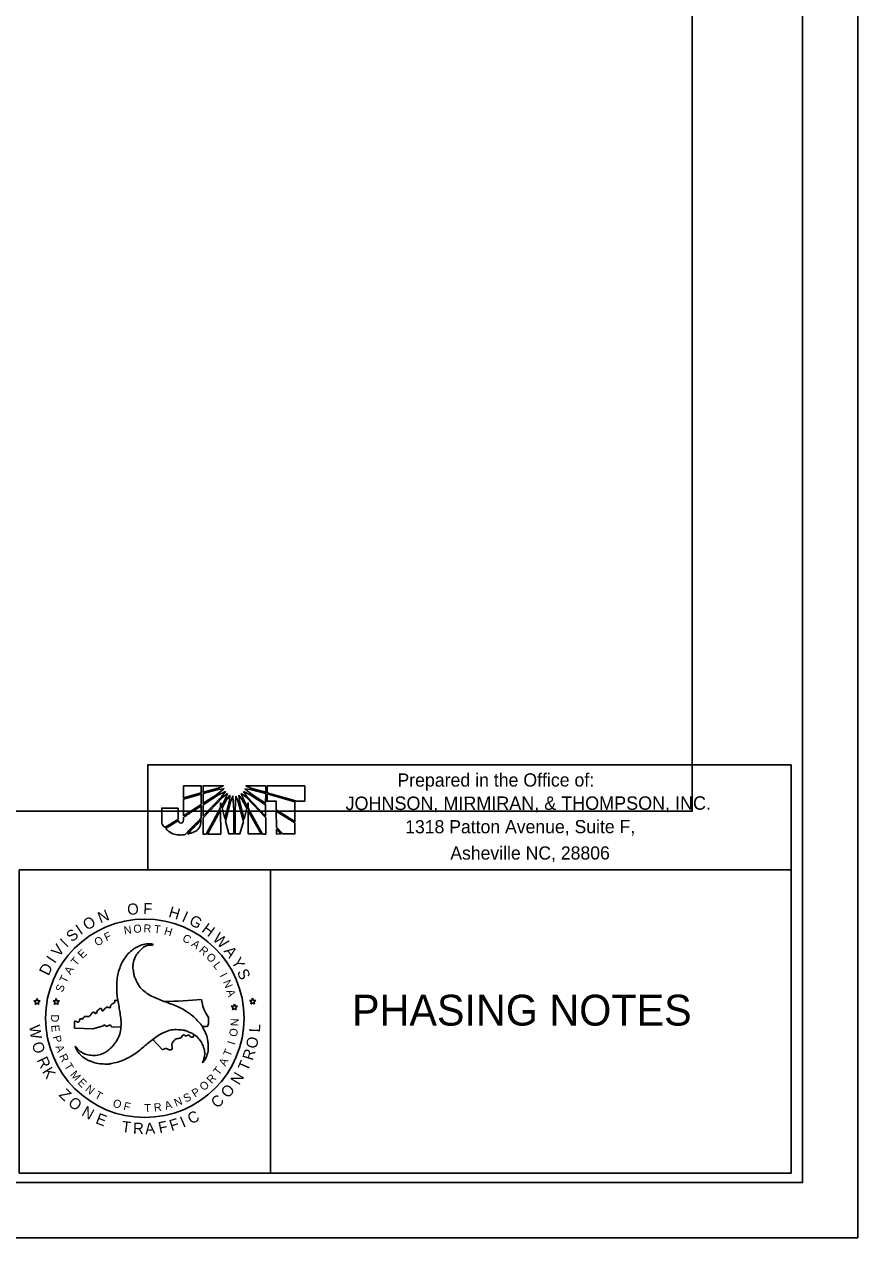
# Model space of a CAD drawing. Extents: x 764226 to 769781, y 650021 to 652521.
# Drawn here: x 767760 to 768137, y 650021 to 650571 of the extents above; entities that cross this region are included whole.
import ezdxf

# ---------------------------------------------------------------- set-up
doc = ezdxf.new("R2010")
doc.units = 0
for name, color, linetype in [('Default', 7, 'Continuous'), ('DEV BORDER CELL', 7, 'Continuous'), ('DEV DOT SWIRL SEAL CELL', 7, 'Continuous'), ('Scratch_Level_0', 7, 'Continuous'), ('Sheet Plan CELL', 7, 'Continuous'), ('Sheet Plot Border Outside CELL', 7, 'Continuous'), ('Sheet Title CELL', 7, 'Continuous'), ('Text', 7, 'Continuous')]:
    doc.layers.add(name, color=color, linetype=linetype)

msp = doc.modelspace()

# ---------------------------------------------------------------- linework, layer by layer
at = {"layer": 'Default'}
for p, q in [((767839.76, 650225.87), (767831.66, 650225.87)), ((767831.66, 650225.87), (767831.67, 650220.5)), ((767831.67, 650220.5), (767839.76, 650222.75)), ((767839.76, 650222.16), (767831.67, 650219.88)), ((767839.76, 650222.75), (767839.76, 650225.87)), ((767839.77, 650217.47), (767839.76, 650222.16)), ((767849.71, 650225.92), (767840.6, 650225.91)), ((767840.6, 650225.91), (767840.6, 650223.02)), ((767840.6, 650223.02), (767847.39, 650224.89)), ((767847.39, 650224.26), (767840.61, 650222.39)), ((767840.61, 650222.39), (767840.61, 650218.01)), ((767840.61, 650218.01), (767846.68, 650221.86)), ((767847.62, 650221.77), (767840.61, 650217.3)), ((767840.61, 650212.25), (767849.14, 650221.14)), ((767846.68, 650221.86), (767850.04, 650224.59)), ((767847.39, 650224.89), (767849.71, 650225.92)), ((767850.04, 650224.59), (767847.39, 650224.26)), ((767850.7, 650223.33), (767847.62, 650221.77)), ((767849.14, 650221.14), (767850.7, 650223.33)), ((767851.64, 650222.36), (767849.49, 650220.7)), ((767850.65, 650219.76), (767851.64, 650222.36)), ((767852.8, 650221.64), (767851.2, 650219.58)), ((767852.58, 650219.14), (767852.8, 650221.64)), ((767854.14, 650221.28), (767853.03, 650218.68)), ((767854.49, 650214.89), (767854.14, 650221.28)), ((767855.48, 650221.28), (767855.07, 650214.89)), ((767856.55, 650218.69), (767855.48, 650221.28)), ((767856.77, 650221.64), (767857.04, 650219.05)), ((767858.34, 650219.58), (767856.77, 650221.64)), ((767857.92, 650222.36), (767858.91, 650219.77)), ((767860.07, 650220.71), (767857.92, 650222.36)), ((767858.87, 650223.34), (767860.43, 650221.11)), ((767862, 650221.78), (767858.87, 650223.34)), ((767859.58, 650224.6), (767862.97, 650221.82)), ((767862.07, 650224.28), (767859.58, 650224.6)), ((767869.01, 650225.9), (767860.03, 650225.93)), ((767860.03, 650225.93), (767862.3, 650224.87)), ((767860.43, 650221.11), (767868.96, 650212.18)), ((767868.96, 650217.36), (767862, 650221.78)), ((767869.01, 650222.37), (767862.07, 650224.28)), ((767862.3, 650224.87), (767869.01, 650222.99)), ((767862.97, 650221.82), (767868.96, 650218.08)), ((767868.96, 650218.08), (767869.01, 650222.37)), ((767869.01, 650222.99), (767869.01, 650225.9)), ((767886.65, 650225.96), (767869.63, 650225.94)), ((767869.63, 650225.94), (767869.64, 650222.81)), ((767869.64, 650222.81), (767869.64, 650222.72)), ((767869.64, 650222.72), (767883.04, 650218.98)), ((767869.64, 650222.24), (767869.64, 650222.19)), ((767882.19, 650218.67), (767869.64, 650222.24)), ((767869.64, 650222.19), (767869.64, 650218.93)), ((767886.66, 650218.98), (767886.65, 650225.96)), ((767831.67, 650219.88), (767831.68, 650212.33)), ((767831.68, 650212.33), (767839.77, 650217.47)), ((767840.61, 650217.3), (767840.61, 650212.25)), ((767849.49, 650220.7), (767840.62, 650211.39)), ((767841.96, 650204.05), (767848.56, 650216.01)), ((767848.56, 650216.01), (767848.56, 650218.15)), ((767848.56, 650218.15), (767848.96, 650216.68)), ((767848.96, 650216.68), (767850.65, 650219.76)), ((767851.2, 650219.58), (767849.19, 650215.92)), ((767849.19, 650215.92), (767850.49, 650211.05)), ((767850.49, 650211.05), (767852.58, 650219.14)), ((767853.03, 650218.68), (767850.76, 650209.93)), ((767858.88, 650209.81), (767856.55, 650218.69)), ((767857.04, 650219.05), (767859.15, 650210.87)), ((767860.44, 650215.79), (767858.34, 650219.58)), ((767858.91, 650219.77), (767860.65, 650216.55)), ((767859.15, 650210.87), (767860.44, 650215.79)), ((767868.97, 650211.34), (767860.07, 650220.71)), ((767860.65, 650216.55), (767861.06, 650218.16)), ((767861.06, 650218.16), (767861.07, 650215.79)), ((767861.07, 650215.79), (767867.54, 650204.07)), ((767868.96, 650212.18), (767868.96, 650217.36)), ((767869.64, 650218.93), (767873.8, 650218.93)), ((767873.8, 650218.93), (767873.8, 650215.04)), ((767882.19, 650209.73), (767882.19, 650218.67)), ((767883.04, 650218.98), (767886.66, 650218.98)), ((767840.62, 650211.39), (767840.62, 650204.04)), ((767848.56, 650214.85), (767842.59, 650204.05)), ((767848.62, 650204.05), (767848.56, 650214.85)), ((767854.5, 650204.1), (767854.49, 650214.89)), ((767855.07, 650214.89), (767855.08, 650204.1)), ((767866.87, 650204.11), (767861.07, 650214.63)), ((767861.07, 650214.63), (767861.08, 650204.1)), ((767868.97, 650204.07), (767868.97, 650211.34)), ((767873.8, 650215.04), (767882.19, 650209.73)), ((767873.8, 650214.37), (767873.81, 650207.13)), ((767882.19, 650209.1), (767873.8, 650214.37)), ((767850.76, 650209.93), (767852.29, 650204.09)), ((767857.32, 650204.1), (767858.88, 650209.81)), ((767873.81, 650207.13), (767876.71, 650204.08)), ((767875.91, 650204.08), (767873.81, 650206.35)), ((767873.81, 650206.35), (767873.81, 650204.07)), ((767882.2, 650204.08), (767882.19, 650209.1)), ((767840.62, 650204.04), (767841.96, 650204.05)), ((767842.59, 650204.05), (767848.62, 650204.05)), ((767852.29, 650204.09), (767854.5, 650204.1)), ((767855.08, 650204.1), (767857.32, 650204.1)), ((767861.08, 650204.1), (767866.87, 650204.11)), ((767867.54, 650204.07), (767868.97, 650204.07)), ((767873.81, 650204.07), (767875.91, 650204.08)), ((767876.71, 650204.08), (767882.2, 650204.08))]:
    msp.add_line(p, q, dxfattribs=at)
for points in [[(767831.67, 650220.5), (767839.76, 650222.75), (767839.76, 650225.87), (767831.66, 650225.87), (767831.67, 650220.5)], [(767831.68, 650212.33), (767839.77, 650217.47), (767839.76, 650222.16), (767831.67, 650219.88), (767831.68, 650212.33)], [(767847.39, 650224.89), (767849.71, 650225.92), (767840.6, 650225.91), (767840.6, 650223.02), (767847.39, 650224.89)], [(767840.61, 650222.39), (767840.61, 650218.01), (767846.68, 650221.86), (767850.04, 650224.59), (767847.39, 650224.26), (767840.61, 650222.39)], [(767840.61, 650217.3), (767840.61, 650212.25), (767849.14, 650221.14), (767850.7, 650223.33), (767847.62, 650221.77), (767840.61, 650217.3)], [(767851.64, 650222.36), (767849.49, 650220.7), (767840.62, 650211.39), (767840.62, 650204.04), (767841.96, 650204.05), (767848.56, 650216.01), (767848.56, 650218.15), (767848.96, 650216.68), (767850.65, 650219.76), (767851.64, 650222.36)], [(767852.8, 650221.64), (767851.2, 650219.58), (767849.19, 650215.92), (767850.49, 650211.05), (767852.58, 650219.14), (767852.8, 650221.64)], [(767853.03, 650218.68), (767850.76, 650209.93), (767852.29, 650204.09), (767854.5, 650204.1), (767854.49, 650214.89), (767854.14, 650221.28), (767853.03, 650218.68)], [(767855.48, 650221.28), (767855.07, 650214.89), (767855.08, 650204.1), (767857.32, 650204.1), (767858.88, 650209.81), (767856.55, 650218.69), (767855.48, 650221.28)], [(767856.77, 650221.64), (767857.04, 650219.05), (767859.15, 650210.87), (767860.44, 650215.79), (767858.34, 650219.58), (767856.77, 650221.64)], [(767857.92, 650222.36), (767858.91, 650219.77), (767860.65, 650216.55), (767861.06, 650218.16), (767861.07, 650215.79), (767867.54, 650204.07), (767868.97, 650204.07), (767868.97, 650211.34), (767860.07, 650220.71), (767857.92, 650222.36)], [(767858.87, 650223.34), (767860.43, 650221.11), (767868.96, 650212.18), (767868.96, 650217.36), (767862, 650221.78), (767858.87, 650223.34)], [(767859.58, 650224.6), (767862.97, 650221.82), (767868.96, 650218.08), (767869.01, 650222.37), (767862.07, 650224.28), (767859.58, 650224.6)], [(767862.3, 650224.87), (767869.01, 650222.99), (767869.01, 650225.9), (767860.03, 650225.93), (767862.3, 650224.87)], [(767869.64, 650222.24), (767869.64, 650222.19), (767869.64, 650218.93), (767873.8, 650218.93), (767873.8, 650215.04), (767882.19, 650209.73), (767882.19, 650218.67), (767869.64, 650222.24)], [(767842.59, 650204.05), (767848.62, 650204.05), (767848.56, 650214.85), (767842.59, 650204.05)], [(767861.08, 650204.1), (767866.87, 650204.11), (767861.07, 650214.63), (767861.08, 650204.1)], [(767873.8, 650214.37), (767873.81, 650207.13), (767876.71, 650204.08), (767882.2, 650204.08), (767882.19, 650209.1), (767873.8, 650214.37), (767873.8, 650214.37)], [(767873.81, 650204.07), (767873.81, 650204.07), (767875.91, 650204.08), (767873.81, 650206.35), (767873.81, 650204.07)]]:
    msp.add_lwpolyline(points, dxfattribs=at)
for points in [[(767829.35, 650215.8), (767829.35, 650215.8), (767821.85, 650215.8), (767821.85, 650215.8), (767821.85, 650215.8), (767821.86, 650211.11), (767821.86, 650211.11), (767821.86, 650211.11), (767821.86, 650210.61), (767821.86, 650210.61), (767821.86, 650209.14), (767822.34, 650207.98), (767823.2, 650207.01), (767823.2, 650207.01), (767829.35, 650210.75), (767829.35, 650210.85), (767829.35, 650210.85), (767829.35, 650215.8), (767829.35, 650215.8)], [(767829.35, 650215.8), (767829.35, 650215.8), (767821.85, 650215.8), (767821.85, 650215.8), (767821.85, 650215.8), (767821.86, 650211.11), (767821.86, 650211.11), (767821.86, 650211.11), (767821.86, 650210.61), (767821.86, 650210.61), (767821.86, 650209.14), (767822.34, 650207.98), (767823.2, 650207.01), (767823.2, 650207.01), (767829.35, 650210.75), (767829.35, 650210.85), (767829.35, 650210.85), (767829.35, 650215.8), (767829.35, 650215.8)], [(767830.52, 650209.06), (767830.04, 650209.06), (767829.62, 650209.32), (767829.45, 650210.22), (767829.45, 650210.22), (767823.64, 650206.62), (767823.64, 650206.62), (767825.43, 650204.74), (767828.29, 650203.62), (767830.71, 650203.62), (767831.34, 650203.62), (767831.82, 650203.68), (767832.49, 650203.81), (767832.49, 650203.81), (767839.77, 650211.35), (767839.77, 650211.35), (767839.77, 650211.35), (767839.77, 650216.8), (767839.77, 650216.8), (767839.77, 650216.8), (767831.68, 650211.65), (767831.68, 650211.65), (767831.68, 650209.61), (767831.18, 650209.06), (767830.52, 650209.06)], [(767830.52, 650209.06), (767830.04, 650209.06), (767829.62, 650209.32), (767829.45, 650210.22), (767829.45, 650210.22), (767823.64, 650206.62), (767823.64, 650206.62), (767825.43, 650204.74), (767828.29, 650203.62), (767830.71, 650203.62), (767831.34, 650203.62), (767831.82, 650203.68), (767832.49, 650203.81), (767832.49, 650203.81), (767839.77, 650211.35), (767839.77, 650211.35), (767839.77, 650211.35), (767839.77, 650216.8), (767839.77, 650216.8), (767839.77, 650216.8), (767831.68, 650211.65), (767831.68, 650211.65), (767831.68, 650209.61), (767831.18, 650209.06), (767830.52, 650209.06)], [(767839.77, 650210.5), (767839.77, 650210.5), (767833.47, 650203.98), (767833.47, 650203.98), (767836.56, 650204.75), (767839.63, 650206.8), (767839.77, 650210.5)], [(767839.77, 650210.5), (767839.77, 650210.5), (767833.47, 650203.98), (767833.47, 650203.98), (767836.56, 650204.75), (767839.63, 650206.8), (767839.77, 650210.5)]]:
    msp.add_open_spline(points, degree=3, dxfattribs=at)
at = {"layer": 'DEV BORDER CELL'}
for points in [[(768112.34, 651096.08), (766612.34, 651096.09), (766612.34, 650046.08), (768112.34, 650046.08)], [(767757.19, 650187.85), (767871.19, 650187.85), (767871.19, 650050.35), (767757.19, 650050.35)], [(768107.19, 650187.85), (767871.19, 650187.85), (767871.19, 650050.35), (768107.19, 650050.35)]]:
    msp.add_lwpolyline(points, close=True, dxfattribs=at)
at = {"layer": 'DEV DOT SWIRL SEAL CELL'}
for p, q in [((767763.92, 650128.51), (767764.8, 650127.87)), ((767765, 650128.51), (767763.92, 650128.51)), ((767764.8, 650127.87), (767764.48, 650126.83)), ((767765.32, 650129.52), (767765, 650128.51)), ((767765.68, 650128.51), (767765.32, 650129.52)), ((767766.77, 650128.51), (767765.68, 650128.51)), ((767765.89, 650127.87), (767766.77, 650128.51)), ((767765.89, 650127.87), (767766.77, 650128.51)), ((767766.21, 650126.83), (767765.89, 650127.87)), ((767766.21, 650126.83), (767765.89, 650127.87)), ((767773.68, 650128.5), (767772.6, 650128.5)), ((767772.6, 650128.5), (767773.48, 650127.86)), ((767773.48, 650127.86), (767773.16, 650126.81)), ((767774, 650129.5), (767773.68, 650128.5)), ((767774.36, 650128.5), (767774, 650129.5)), ((767775.45, 650128.5), (767774.36, 650128.5)), ((767774.56, 650127.86), (767775.45, 650128.5)), ((767774.89, 650126.81), (767774.56, 650127.86)), ((767862.73, 650128.66), (767861.64, 650128.66)), ((767861.64, 650128.66), (767862.53, 650128.01)), ((767862.53, 650128.01), (767862.2, 650126.97)), ((767862.2, 650126.97), (767863.05, 650127.61)), ((767863.05, 650129.66), (767862.73, 650128.66)), ((767863.41, 650128.66), (767863.05, 650129.66)), ((767863.05, 650127.61), (767863.93, 650126.97)), ((767864.49, 650128.66), (767863.41, 650128.66)), ((767863.61, 650128.01), (767864.49, 650128.66)), ((767863.93, 650126.97), (767863.61, 650128.01)), ((767764.48, 650126.83), (767765.32, 650127.47)), ((767765.32, 650127.47), (767766.21, 650126.83)), ((767765.32, 650127.47), (767766.21, 650126.83)), ((767773.16, 650126.81), (767774, 650127.46)), ((767774, 650127.46), (767774.89, 650126.81)), ((767854.45, 650126.01), (767853.37, 650126.01)), ((767853.37, 650126.01), (767854.25, 650125.37)), ((767854.25, 650125.37), (767853.93, 650124.33)), ((767853.93, 650124.33), (767854.77, 650124.97)), ((767854.77, 650127.01), (767854.45, 650126.01)), ((767855.13, 650126.01), (767854.77, 650127.01)), ((767854.77, 650124.97), (767855.65, 650124.33)), ((767856.22, 650126.01), (767855.13, 650126.01)), ((767855.33, 650125.37), (767856.22, 650126.01)), ((767855.65, 650124.33), (767855.33, 650125.37)), ((767782.25, 650116.07), (767782.33, 650118.73)), ((767795.44, 650117.17), (767790.64, 650115.76)), ((767799.14, 650116.61), (767803.36, 650116.57)), ((767790.64, 650115.76), (767782.25, 650116.07)), ((767817.89, 650110.99), (767822.2, 650106.32))]:
    msp.add_line(p, q, dxfattribs=at)
for start, end in [(265.6785, 265.9762), (271.2035, 275.3236)]:
    msp.add_arc((767818.28, 650361.25), 233.19, start, end, dxfattribs=at)
for points in [[(767782.66, 650107.96), (767784.4, 650105.95), (767786.58, 650104.55), (767789.07, 650103.9), (767791.89, 650103.74), (767794.76, 650104.41), (767796.67, 650105.38), (767797.47, 650106.02), (767798.87, 650107.13), (767799.86, 650108.2), (767801.53, 650110.56), (767802.82, 650113.35), (767803.35, 650116.55), (767803.38, 650116.82), (767803.35, 650119.82), (767802.95, 650122.86), (767802.52, 650125.78), (767801.98, 650128.82), (767801.5, 650131.82), (767801.45, 650134.75), (767801.64, 650138.11), (767802.12, 650140.98), (767803.06, 650143.93), (767803.57, 650145.33), (767804.27, 650146.45), (767806.01, 650149.11), (767808.29, 650151.26), (767809.8, 650152.39), (767811.22, 650153.14), (767811.46, 650153.27), (767814.31, 650154.18), (767817.1, 650154.29), (767818.04, 650154.05)], [(767818.12, 650154.13), (767818.04, 650154.05), (767815.46, 650153.57), (767813.13, 650152.36), (767811.33, 650150.53), (767809.8, 650148.2), (767808.94, 650145.35), (767808.8, 650143.23), (767808.99, 650142.21), (767809.23, 650140.44), (767809.64, 650139.04), (767810.9, 650136.44), (767812.64, 650133.92), (767815.17, 650131.85), (767815.38, 650131.69), (767817.96, 650130.21), (767820.83, 650129.03), (767823.57, 650127.96), (767826.44, 650126.91), (767829.28, 650125.78), (767831.86, 650124.39), (767834.68, 650122.56), (767836.91, 650120.71), (767839, 650118.43), (767839.97, 650117.27), (767840.59, 650116.09), (767842.04, 650113.27), (767842.73, 650110.21), (767842.98, 650108.34), (767842.92, 650106.72), (767842.92, 650106.46), (767842.25, 650103.53), (767840.94, 650101.06), (767840.29, 650100.39)], [(767782.33, 650118.73), (767782.25, 650118.98), (767782.7, 650119.26), (767783.94, 650118.75), (767784.56, 650119.29), (767784.53, 650119.83), (767785.04, 650120.37), (767785.89, 650120.19), (767786.65, 650121.16), (767787.36, 650121.35), (767788.86, 650121.35), (767790.64, 650123.13), (767791.37, 650123.25), (767791.57, 650122.77), (767792.02, 650122.68), (767792.81, 650124.15), (767793.01, 650124.35), (767794.37, 650124.91), (767794.73, 650124.63), (767794.85, 650123.98), (767795.04, 650123.87), (767795.5, 650124.18), (767796.12, 650124.97), (767797.25, 650125.57), (767798.55, 650125.39), (767798.77, 650126.47), (767800.3, 650127.49), (767800.61, 650128.11), (767800.7, 650128.73)], [(767840.22, 650116.84), (767842.69, 650117.14), (767843.05, 650119.09), (767843.08, 650120.73), (767842.06, 650122.63), (767840.54, 650126.1), (767839.92, 650129.07)], [(767799.14, 650116.61), (767798.8, 650117.26), (767798.13, 650117.45), (767797.19, 650116.97), (767796.51, 650117), (767795.75, 650117.57), (767795.44, 650117.17)], [(767840.29, 650100.39), (767841.15, 650102.86), (767841.29, 650105.46), (767840.59, 650107.96), (767839.33, 650110.45), (767837.31, 650112.6), (767835.54, 650113.78), (767834.55, 650114.13), (767832.94, 650114.83), (767831.46, 650115.15), (767828.61, 650115.39), (767825.53, 650115.13), (767822.49, 650113.97), (767822.25, 650113.86), (767819.68, 650112.33), (767817.23, 650110.48), (767814.9, 650108.66), (767812.56, 650106.67), (767810.17, 650104.74), (767807.68, 650103.23), (767804.67, 650101.7), (767801.96, 650100.71), (767798.95, 650100.04), (767797.45, 650099.77), (767796.13, 650099.82), (767792.99, 650099.99), (767789.96, 650100.9), (767788.24, 650101.62), (767786.87, 650102.51), (767786.63, 650102.64), (767784.43, 650104.66), (767782.95, 650107.02), (767782.66, 650107.96)], [(767822.2, 650106.32), (767823.9, 650106.83), (767825.31, 650106.29), (767825.99, 650106.18), (767826.55, 650106.6), (767826.38, 650108.72), (767826.86, 650109.71), (767829.15, 650111.41), (767830.57, 650111.72), (767831.61, 650113.02), (767832.03, 650112.99), (767832.68, 650112.62), (767834.13, 650112.91), (767835.28, 650111.97), (767835.96, 650112.03), (767836.5, 650113.09)]]:
    msp.add_spline(points, degree=3, dxfattribs=at)
at = {"layer": 'Scratch_Level_0'}
msp.add_lwpolyline([(768062.34, 651046.08), (766662.34, 651046.09), (766662.34, 650096.08), (767541.19, 650096.08), (767541.19, 650214.35), (768062.34, 650214.35)], close=True, dxfattribs=at)
at = {"layer": 'Sheet Plan CELL'}
msp.add_lwpolyline([(768107.19, 650235.37), (767815.52, 650235.37), (767815.52, 650187.85), (768107.19, 650187.85)], close=True, dxfattribs=at)
at = {"layer": 'Sheet Plot Border Outside CELL'}
msp.add_lwpolyline([(766449.34, 650021.08), (768137.34, 650021.08), (768137.34, 651121.08), (766449.34, 651121.08)], close=True, dxfattribs=at)
at = {"layer": 'Text'}
msp.add_circle((767814.19, 650120.56), 44.97, dxfattribs=at)

# ---------------------------------------------------------------- texts
at = {"layer": 'Default'}
msp.add_text('PHASING NOTES', height=14, dxfattribs=at).set_placement((767908.11, 650117.23))
at = {"layer": 'DEV DOT SWIRL SEAL CELL'}
for s, height, rotation, p in [('O', 5.04, 5.7649, (767806.45, 650167.29)), ('F', 5.04, 357.2575, (767813.4, 650167.84)), ('O', 5.04, 30.0935, (767787.94, 650160.18)), ('N', 5.04, 21.5861, (767794.05, 650163.56)), ('H', 5.04, 343.454, (767824.63, 650166.55)), ('I', 5.04, 335.804, (767830.63, 650164.68)), ('G', 5.04, 331.5167, (767833.86, 650163.29)), ('S', 5.04, 40.5848, (767781.2, 650154.84)), ('I', 5.04, 34.3808, (767785.06, 650158.15)), ('N', 3.63, 9.0227, (767804.97, 650158.5)), ('O', 3.63, 3.9446, (767809.11, 650159.22)), ('R', 3.63, 358.8665, (767813.59, 650159.49)), ('H', 3.63, 343.6322, (767822.67, 650158.63)), ('H', 5.04, 323.4632, (767839.61, 650160.04)), ('I', 5.04, 44.8722, (767778.74, 650152.31)), ('O', 3.63, 29.335, (767792.54, 650153.03)), ('F', 3.63, 24.2569, (767796.75, 650155.38)), ('C', 3.63, 333.4761, (767830.9, 650155.71)), ('A', 3.63, 323.3199, (767835, 650153.59)), ('W', 5.04, 315.8133, (767844.61, 650156.24)), ('V', 5.04, 51.5806, (767775.3, 650148.02)), ('E', 3.63, 44.5692, (767785.93, 650147.35)), ('R', 3.63, 318.2418, (767838.49, 650151.03)), ('O', 3.63, 313.1637, (767841.7, 650148.12)), ('A', 5.04, 306.7762, (767849.79, 650150.94)), ('D', 5.04, 63.459, (767770.52, 650139.54)), ('I', 5.04, 55.8679, (767773.37, 650145.07)), ('T', 3.63, 49.6473, (767783.07, 650144.04)), ('L', 3.63, 308.0856, (767844.92, 650144.45)), ('Y', 5.04, 299.7484, (767853.21, 650146.3)), ('T', 3.63, 64.8816, (767778.57, 650136.26)), ('A', 3.63, 59.8035, (767780.51, 650140.05)), ('I', 3.63, 297.9295, (767847.96, 650139.94)), ('S', 5.04, 293.2249, (767855.85, 650141.64)), ('S', 3.63, 69.9597, (767776.98, 650132.12)), ('N', 3.63, 292.8514, (767849.48, 650137.04)), ('A', 3.63, 287.7733, (767851.08, 650132.98)), ('D', 3.63, 270.272, (767771.64, 650122.26)), ('E', 3.63, 275.3501, (767771.75, 650117.4)), ('N', 3.63, 87.733, (767856.63, 650116.9)), ('P', 3.63, 285.5063, (767772.36, 650112.19)), ('O', 3.63, 82.9269, (767856, 650112.03)), ('A', 3.63, 290.5843, (767773.56, 650107.74)), ('T', 3.63, 67.6926, (767852.93, 650102.88)), ('I', 3.63, 72.7707, (767854.92, 650108.27)), ('R', 3.63, 295.6624, (767775.23, 650103.4)), ('T', 3.63, 300.7405, (767777.51, 650098.99)), ('A', 3.63, 62.6145, (767850.7, 650098.54)), ('M', 3.63, 310.8967, (767780.13, 650094.9)), ('R', 3.63, 47.3803, (767844.49, 650090.66)), ('T', 3.63, 52.4584, (767847.75, 650094.4)), ('E', 3.63, 315.9748, (767783.47, 650091.08)), ('N', 3.63, 321.0529, (767786.89, 650087.92)), ('O', 3.63, 42.3022, (767840.96, 650087.39)), ('T', 3.63, 331.209, (767791.13, 650084.68)), ('O', 3.63, 341.3652, (767799.34, 650080.66)), ('N', 3.63, 21.9899, (767828.35, 650080.39)), ('S', 3.63, 27.068, (767832.76, 650082.27)), ('P', 3.63, 32.146, (767836.89, 650084.57)), ('F', 3.63, 346.4433, (767804.26, 650079.19)), ('T', 3.63, 1.6775, (767814.02, 650077.99)), ('R', 3.63, 6.7556, (767818.51, 650078.23)), ('A', 3.63, 16.9118, (767823.77, 650079))]:
    msp.add_text(s, height=height, rotation=rotation, dxfattribs=at).set_placement(p)
at = {"layer": 'Sheet Title CELL'}
for s, height, p in [('Prepared in the Office of:', 5.9987, (767928.69, 650225.52)), ('JOHNSON, MIRMIRAN, & THOMPSON, INC.', 6.0929, (767905.17, 650214.92)), ('1318 Patton Avenue, Suite F,', 5.9679, (767932.21, 650204.37)), ('Asheville NC, 28806', 5.9679, (767952.66, 650192.45))]:
    msp.add_text(s, height=height, rotation=0.0516, dxfattribs=at).set_placement(p)
at = {"layer": 'Text'}
for s, height, rotation, p in [('T', 3.63, 353.7884, (767818.22, 650159.27)), ('W', 5.04, 278.15, (767761.71, 650117.18)), ('L', 5.04, 87.429, (767866.39, 650114.11)), ('O', 5.04, 78.9896, (767864.88, 650106.52)), ('O', 5.04, 287.1147, (767762.87, 650109.05)), ('R', 5.04, 72.7519, (767863.05, 650101.09)), ('R', 5.04, 295.5541, (767765.12, 650101.64)), ('T', 5.04, 66.881, (767860.8, 650096.2)), ('K', 5.04, 301.7918, (767767.46, 650096.42)), ('N', 5.04, 58.892, (767856.97, 650089.95)), ('O', 5.04, 50.4526, (767852.01, 650084.01)), ('Z', 5.04, 316.1688, (767774.92, 650085.57)), ('O', 5.04, 322.5233, (767779.03, 650081.44)), ('C', 5.04, 43.0807, (767847.01, 650079.46)), ('N', 5.04, 330.9626, (767785.15, 650076.7)), ('C', 5.04, 28.0033, (767835.19, 650072.34)), ('E', 5.04, 338.9517, (767791.53, 650073.09)), ('T', 5.04, 352.6948, (767803.46, 650069.07)), ('R', 5.04, 358.5656, (767808.78, 650068.24)), ('A', 5.04, 4.8034, (767814.49, 650067.96)), ('F', 5.04, 11.7751, (767820.88, 650068.39)), ('F', 5.04, 17.7627, (767826.28, 650069.37)), ('I', 5.04, 23.7503, (767831.55, 650070.91))]:
    msp.add_text(s, height=height, rotation=rotation, dxfattribs=at).set_placement(p)

doc.saveas('drawing.dxf')
